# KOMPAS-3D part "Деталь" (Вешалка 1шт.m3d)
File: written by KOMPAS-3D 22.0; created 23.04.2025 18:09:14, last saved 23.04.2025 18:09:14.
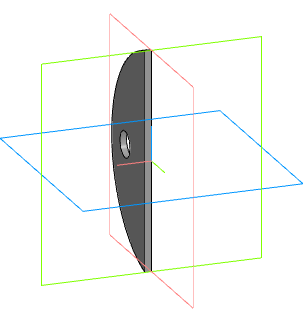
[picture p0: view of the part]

Document properties: Автор: Admin; Полное имя файла: D:\28.11.2016\3D модели\Абилимпикс\2025\Воронка квадратная\Вешалка 1шт.m3d

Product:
- Part/product: Деталь
    Масса: 0.008452

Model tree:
1. Эскиз:1
2. Элемент выдавливания:1
     Расстояние 1 = 1.5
